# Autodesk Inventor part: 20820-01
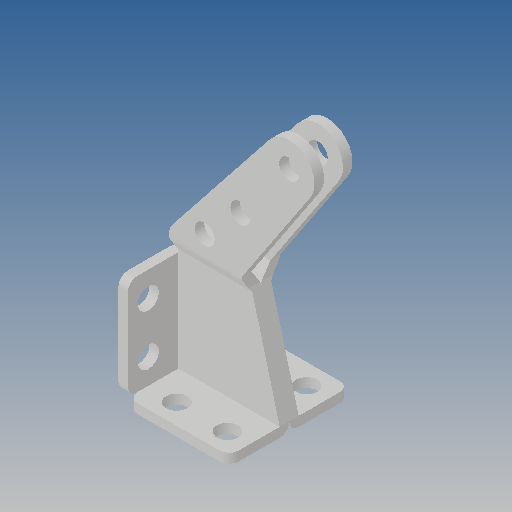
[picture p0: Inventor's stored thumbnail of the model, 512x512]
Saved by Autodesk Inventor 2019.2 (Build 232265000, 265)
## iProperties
Created: 2011-12
Part Number: 20820-01
Material: Ogólny
Document SubType Name: Modeling
Designer: CADENGINEERING4
Density: 1 g/cm^3
Appearance: Domyślna
Author: CADENGINEERING4
Revision Number: ÈÎºÎ
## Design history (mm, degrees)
feature "Ô²½Ç2"
feature "Ô²½Ç1"
feature "¾µÏò1[1]"
feature "¾µÏò1[2]"
node "Bryła1"
node "Bryła2"
node "Bryła3"
node "Bryła4"
